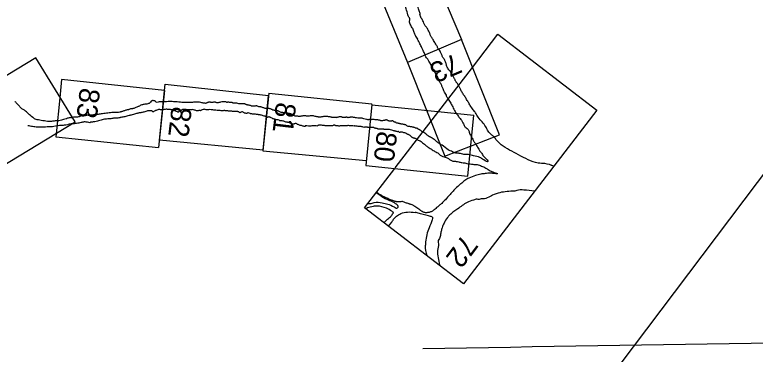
# Model space of a CAD drawing. Extents: x 3879599 to 3900814, y 146526 to 168888.
# Drawn here: x 3883542 to 3885674, y 156492 to 157470 of the extents above; entities that cross this region are included whole.
import ezdxf

# ---------------------------------------------------------------- set-up
doc = ezdxf.new("R2010")
doc.units = 0
for name, color, linetype in [('V-ANNO-NPLT', 7, 'Continuous'), ('V-GRID-FRAM', 7, 'Continuous'), ('V-GRID-MAJR', 7, 'Continuous')]:
    doc.layers.add(name, color=color, linetype=linetype)

msp = doc.modelspace()

# ---------------------------------------------------------------- linework, layer by layer
at = {"layer": 'V-ANNO-NPLT'}
for p, q in [((3884828.5, 157398.7), (3884672.7, 157332)), ((3884559.4, 156925.5), (3884558.4, 156925.5)), ((3884618.4, 156860.4), (3884627.5, 156871.7))]:
    msp.add_line(p, q, dxfattribs=at)
for points in [[(3884713, 157670.7), (3884559.8, 157608.4), (3884672.7, 157332)], [(3884713, 157670.7), (3884828.5, 157398.7)], [(3884933.3, 157413.5), (3885217.9, 157194.6), (3884833.8, 156694.8), (3884549, 156913.5)], [(3884860.1, 157318.3), (3884933.3, 157413.5)], [(3884828.5, 157398.7), (3884672.7, 157332), (3884780.8, 157062.4), (3884937.4, 157123.8)], [(3884937.4, 157123.8), (3884828.5, 157398.7)], [(3883602.8, 157345.6), (3883333.7, 157182.3), (3883446.8, 156998.1), (3883716.1, 157161.4)], [(3883716.1, 157161.4), (3883602.8, 157345.6)], [(3884637.5, 157028.6), (3884860.1, 157318.3)], [(3883973.7, 157251.6), (3883677.2, 157283.4), (3883672, 157230.6)], [(3883958.8, 157108.9), (3883975.6, 157269.5), (3884273, 157237)], [(3883973.7, 157251.6), (3883956.5, 157087.1)], [(3884273.7, 157243.6), (3884256.8, 157077.8), (3884554.2, 157050)], [(3884257, 157080.1), (3884273, 157237)], [(3884273.7, 157243.6), (3884570.4, 157212.9)], [(3883672, 157230.6), (3883661.8, 157126.9)], [(3884570.3, 157211.4), (3884552.7, 157035.1), (3884847.1, 157005.1), (3884855.7, 157092.8)], [(3884570.2, 157210.5), (3884760.7, 157191.1)], [(3884570.3, 157211), (3884570.4, 157212.9)], [(3884759.9, 157190.9), (3884864.2, 157180.3)], [(3884855.7, 157092.8), (3884864.2, 157180.3)], [(3883661.8, 157126.9), (3883660.9, 157117.7), (3883956.5, 157087.1)], [(3884257, 157080.1), (3883958.8, 157108.9)], [(3884554.2, 157050), (3884554.2, 157050)], [(3884549, 156913.5), (3884636.2, 157027)]]:
    msp.add_lwpolyline(points, dxfattribs=at)
for points in [[(3884674.3, 157469.8), (3884669.1, 157487.1), (3884666, 157498), (3884662.6, 157506.4), (3884660.2, 157516.1), (3884658, 157524.6), (3884655.6, 157532.1), (3884654.3, 157538.2), (3884652.2, 157548.3), (3884650.7, 157561.3), (3884649.3, 157577.1), (3884649.3, 157587.7), (3884647.8, 157598.5), (3884647.9, 157605.7), (3884647.5, 157615), (3884647.4, 157618.4)], [(3884752.8, 157387.7), (3884749.7, 157393.1), (3884746.5, 157398.9), (3884741.5, 157406.1), (3884737.8, 157413.7), (3884733.9, 157422.9), (3884731.6, 157427.5), (3884729, 157432.4), (3884723.7, 157438), (3884720.2, 157445.9), (3884717.1, 157452.6), (3884715.3, 157456.8), (3884712.4, 157460.1), (3884710.7, 157465.6), (3884708.8, 157470.8), (3884709.3, 157473.2), (3884707.7, 157478.7), (3884705.8, 157483.9), (3884703.5, 157490.4), (3884702.2, 157495.2), (3884700.9, 157499.4), (3884700, 157501.8)], [(3884687, 157431), (3884686.2, 157432.5), (3884683.6, 157437.9), (3884680.9, 157442.8), (3884679, 157448.6), (3884678.6, 157452.1), (3884680, 157455.7), (3884678.3, 157461.2), (3884676.1, 157464.8), (3884674.3, 157469.8)], [(3884687, 157431), (3884691.1, 157419.7), (3884694.7, 157410.8), (3884701.8, 157399.2)], [(3884724.1, 157354), (3884722.2, 157359.2), (3884719.4, 157363.8), (3884716.2, 157370.9), (3884712.9, 157377.3), (3884710.2, 157383.2), (3884707.2, 157389.3), (3884703.6, 157395.9), (3884701.9, 157399.1), (3884701.8, 157399.2)], [(3884819.8, 157265.9), (3884818.7, 157268.3), (3884817.1, 157271.4), (3884815.3, 157273.3), (3884813.6, 157274.7), (3884811.9, 157277.9), (3884810.6, 157280.3), (3884808.9, 157284), (3884807.3, 157286.7), (3884805.5, 157290.9), (3884803.4, 157293.5), (3884801.3, 157298.9), (3884799.4, 157301.8), (3884797.1, 157306), (3884793.6, 157309.2), (3884790, 157314), (3884787.6, 157318.6), (3884785.5, 157323.6), (3884784.3, 157327.8), (3884783.6, 157331.6), (3884781.5, 157336.1), (3884779.5, 157340.5), (3884777.3, 157344.1), (3884774.9, 157347), (3884773.2, 157350.6), (3884771.7, 157354.6), (3884770, 157358.3), (3884768.2, 157362.5), (3884765.3, 157367.6), (3884761.7, 157371.9), (3884758, 157379), (3884755.5, 157383.4), (3884752.8, 157387.7)], [(3884790.1, 157227.1), (3884785.6, 157235.6), (3884783.7, 157241.3), (3884779.7, 157246.8), (3884776.6, 157254), (3884773.1, 157261.9), (3884769.6, 157269.8), (3884767.3, 157273.9), (3884763.6, 157282), (3884760.5, 157288.7), (3884757.5, 157294.3), (3884754.4, 157298.6), (3884752.6, 157303.3), (3884751.1, 157307.8), (3884749.6, 157311.3), (3884745.7, 157313.9), (3884744, 157318.1), (3884741.7, 157321.8), (3884740, 157325.5), (3884737.9, 157330.4), (3884734.4, 157336), (3884729.9, 157343.7), (3884726.1, 157348.2), (3884724.1, 157354)], [(3884927.6, 157110.8), (3884921.1, 157118.9), (3884913.9, 157124.7), (3884905.6, 157134.2), (3884898.1, 157147.2), (3884888.3, 157160.9), (3884876.3, 157174.5), (3884868.8, 157187.4), (3884862.4, 157195.5), (3884853.6, 157208.3), (3884847.7, 157218.1), (3884841.8, 157228.2), (3884836.2, 157237.2), (3884832.9, 157241.8), (3884827.4, 157251.1), (3884823.8, 157259), (3884819.8, 157265.9)], [(3883594.2, 157174.2), (3883581.7, 157184.7), (3883570.7, 157194.5), (3883562.5, 157199.2), (3883555.6, 157206.6), (3883548.1, 157214), (3883545.1, 157217.9), (3883542.5, 157219.8)], [(3883942.5, 157221.7), (3883939.9, 157222.6), (3883938, 157222.2), (3883935.3, 157220.8), (3883930.3, 157215.5), (3883927.3, 157213.7), (3883922.8, 157212.5), (3883917.1, 157211.8), (3883911.7, 157211), (3883908.2, 157209.9), (3883903.2, 157208.1), (3883898.8, 157205.8), (3883895.5, 157204.6), (3883891.3, 157202.5), (3883886.6, 157200.7), (3883882.7, 157199.4), (3883879.5, 157199), (3883872, 157197.3), (3883870.1, 157196.2), (3883866.4, 157195.6), (3883862.2, 157194.7), (3883858.2, 157193.4), (3883854, 157191.7), (3883850.8, 157190.6), (3883848.4, 157190), (3883845.6, 157189.3), (3883844.8, 157189)], [(3884037, 157217.2), (3884028.2, 157217.1), (3884019, 157217.7), (3884009.8, 157218.6), (3883999.1, 157219.4), (3883992.8, 157219.6), (3883984, 157219.5), (3883974.4, 157219.1), (3883970.1, 157219.4), (3883963.8, 157219.2), (3883958.4, 157219), (3883952.7, 157217.4), (3883947.6, 157219.5), (3883946.3, 157221.5), (3883944, 157221.8), (3883942.5, 157221.7)], [(3884095, 157215.3), (3884094.3, 157215), (3884091.1, 157214.6), (3884087.1, 157215.2), (3884083.2, 157215.7), (3884077.9, 157216.7), (3884070.3, 157218), (3884062.9, 157217.7), (3884060.2, 157218), (3884054.4, 157217.1), (3884045.5, 157216.9), (3884042.7, 157217.1), (3884039.3, 157217.3), (3884037, 157217.2)], [(3884105.3, 157217.7), (3884103.2, 157218.1), (3884100.3, 157217.7), (3884097.7, 157217), (3884096, 157216.1), (3884095, 157215.3)], [(3884154.7, 157217.5), (3884153.2, 157217.4), (3884149.8, 157218.5), (3884146.3, 157219), (3884142.4, 157218.9), (3884134.6, 157218.1), (3884129.9, 157216.6), (3884125.5, 157216.3), (3884121.9, 157216.6), (3884119.9, 157217.8), (3884114.7, 157217.8), (3884110, 157217.1), (3884106.7, 157217.4), (3884105.3, 157217.7)], [(3884168.1, 157216.6), (3884165, 157217.1), (3884162.1, 157217.4), (3884158.4, 157217.5), (3884156.1, 157217.9), (3884154.7, 157217.5)], [(3884206.8, 157211.9), (3884205.5, 157212.5), (3884203.9, 157212.9), (3884199.7, 157213), (3884195.8, 157213.2), (3884191.5, 157213.1), (3884187.4, 157212.8), (3884181.4, 157214.7), (3884176.6, 157215), (3884172.6, 157215.3), (3884169.8, 157215.9), (3884168.1, 157216.6)], [(3884790.1, 157227.1), (3884797.4, 157214.7), (3884803, 157204.3), (3884810, 157190.7), (3884816.7, 157181.4), (3884822.5, 157172.9), (3884826.6, 157168.3), (3884831.5, 157160.5), (3884836.1, 157150.9), (3884838.1, 157147.2), (3884842.3, 157144.2), (3884847.2, 157139.3), (3884850.9, 157131.4), (3884852.6, 157126.1), (3884856.1, 157119.3), (3884862.3, 157108.5), (3884866.2, 157101.7), (3884871.8, 157093.4), (3884877.9, 157082.1), (3884883.1, 157075), (3884883.9, 157074.3), (3884889.8, 157064.7), (3884897.3, 157056.7), (3884902.3, 157051.8), (3884904.5, 157047.1), (3884892.4, 157051.8), (3884881.1, 157058.8), (3884863.4, 157063.2), (3884848.7, 157066.9), (3884835.5, 157067.4), (3884822, 157070.3), (3884811.9, 157071.4), (3884802.1, 157075.3), (3884790.5, 157080.6), (3884772.4, 157094), (3884763, 157099.5), (3884755.2, 157105.6), (3884747.3, 157112.1), (3884735.9, 157118.4), (3884728.1, 157124.8), (3884717, 157132.9)], [(3883942.2, 157190.1), (3883941.4, 157190.2), (3883940, 157190.4), (3883938.5, 157192.2), (3883934.3, 157193), (3883930, 157193.2), (3883924.8, 157192.8), (3883919.8, 157191.3), (3883914.1, 157189.1), (3883909.5, 157188.6), (3883905, 157187.7), (3883900.2, 157187), (3883896.2, 157186.3), (3883892.4, 157184.9), (3883887.5, 157183.2), (3883880, 157181.5), (3883875.3, 157180.1), (3883871.3, 157179.1), (3883864.5, 157177.8), (3883859.3, 157175.8), (3883853.7, 157175.1), (3883847.4, 157173.7), (3883844.7, 157173.2)], [(3884018.3, 157194.1), (3884015.2, 157192.3), (3884014.7, 157190.8), (3884013.6, 157189.5), (3884011.8, 157189.6), (3884009, 157190.9), (3884005.6, 157192), (3884000.2, 157193.7), (3883995.2, 157195.5), (3883990.4, 157196.7), (3883983.6, 157196.7), (3883980.4, 157197.6), (3883975.3, 157197.2), (3883972.3, 157196.7), (3883966.9, 157196.4), (3883961.9, 157196.2), (3883957.9, 157196.8), (3883949.6, 157194.1), (3883946.1, 157193), (3883942.2, 157190.1)], [(3884077.6, 157193.4), (3884075.3, 157193.7), (3884072.5, 157193.7), (3884068.3, 157192.9), (3884063.6, 157194), (3884059.6, 157195.3), (3884054.6, 157196.4), (3884049.2, 157196.1), (3884043.5, 157195.9), (3884039.6, 157196.1), (3884032.5, 157196.6), (3884027.1, 157196.7), (3884023.1, 157196.1), (3884021.1, 157194.1), (3884018.3, 157194.1)], [(3884136.3, 157193.3), (3884130.1, 157194.2), (3884124.7, 157194.4), (3884118.6, 157195.1), (3884112.2, 157195.6), (3884102.8, 157196.4), (3884097, 157195.9), (3884093.7, 157195.9), (3884088, 157197.6), (3884084.7, 157196.7), (3884079.9, 157194.7), (3884078.9, 157194.2), (3884076.9, 157192.9)], [(3884183.7, 157191.2), (3884179.8, 157191.2), (3884177.2, 157190.7), (3884171.6, 157191), (3884167.2, 157191.9), (3884161.4, 157192.4), (3884157.9, 157192.5), (3884153.8, 157192.9), (3884149.8, 157193.2), (3884147.2, 157193.7), (3884144.2, 157193.5), (3884140.4, 157192.7), (3884137.8, 157193.1), (3884136.3, 157193.3)], [(3884214.9, 157209.5), (3884213.4, 157209.6), (3884211.6, 157210.1), (3884209.1, 157210.7), (3884208.2, 157211.1), (3884206.8, 157211.9)], [(3884281.8, 157197.2), (3884278.5, 157198.3), (3884275.1, 157199.7), (3884270.6, 157199.8), (3884264.7, 157200), (3884261.6, 157200.5), (3884257.8, 157201.9), (3884253.9, 157203.1), (3884250.4, 157204.3), (3884247, 157204.5), (3884244.8, 157204.9), (3884241.2, 157206.1), (3884239.3, 157207.4), (3884236.4, 157207), (3884232.6, 157206.3), (3884227.7, 157206.6), (3884224.1, 157206.9), (3884221.3, 157208.2), (3884217.6, 157208.9), (3884214.9, 157209.5)], [(3884353.5, 157177.5), (3884349.4, 157178.1), (3884345.4, 157179.4), (3884342.7, 157180.6), (3884339.2, 157183.4), (3884334.6, 157184.5), (3884331.1, 157185.4), (3884328.9, 157185.8), (3884325, 157186.7), (3884319, 157186.9), (3884315.9, 157187.4), (3884312.6, 157188.1), (3884309.2, 157188.6), (3884305.3, 157189.8), (3884302.6, 157191.7), (3884299.2, 157192.7), (3884296.1, 157193.3), (3884292.8, 157194), (3884290.1, 157194.2), (3884287.3, 157194.8), (3884284, 157195.9), (3884282.4, 157197.1), (3884281.8, 157197.2)], [(3883690.3, 157169.7), (3883683, 157167.7), (3883676.7, 157166), (3883668.9, 157164.2), (3883661.1, 157164.6), (3883656.1, 157163.4), (3883645.3, 157162.7), (3883636.3, 157162.6), (3883627.6, 157163.8), (3883618.6, 157165.2), (3883610.2, 157166.7), (3883603.8, 157168.3), (3883599.4, 157170.1), (3883595.1, 157173.5), (3883594.2, 157174.2)], [(3883751.4, 157180.4), (3883748.4, 157179.9), (3883745.2, 157178.8), (3883742.5, 157178.2), (3883739.5, 157178.4), (3883736.7, 157178.8), (3883731.4, 157177.2), (3883728.2, 157176.1), (3883723.4, 157175.1), (3883719.4, 157174.6), (3883714.7, 157174.4), (3883711.2, 157174.5), (3883707.8, 157173.1), (3883704.3, 157173.2), (3883700.8, 157173.3), (3883696.4, 157172.3), (3883692.1, 157170.8), (3883690.3, 157169.7)], [(3883844.8, 157189), (3883836.8, 157188.3), (3883831.8, 157188.1), (3883825.5, 157188.3), (3883810.1, 157186.4), (3883794.5, 157184.7), (3883782, 157182.7), (3883772.7, 157182.4), (3883765, 157180.8), (3883758, 157179.7), (3883751.4, 157180.4)], [(3883844.8, 157173.3), (3883839.5, 157171.9), (3883826.8, 157171.4), (3883816.8, 157169.8), (3883803.4, 157169.2), (3883791, 157166.2), (3883776.4, 157162.7), (3883768.5, 157160.9), (3883763.3, 157160.5), (3883758.5, 157158.6), (3883758.4, 157158.2)], [(3884267.5, 157175.2), (3884264.8, 157177), (3884262.9, 157177.2), (3884257.6, 157178.6), (3884253.1, 157180.2), (3884248.7, 157181.5), (3884244.3, 157181.8), (3884241.2, 157182.3), (3884235.4, 157183.1), (3884230.2, 157183.4), (3884226.7, 157183.5), (3884223.2, 157184.4), (3884219.7, 157185.3), (3884214.3, 157187), (3884211.7, 157186.2), (3884210.6, 157185.5), (3884206.4, 157185.9), (3884203.6, 157186.5), (3884201.3, 157188.4), (3884198.4, 157189.7), (3884194.1, 157189.6), (3884192, 157188.1), (3884190.8, 157187.4), (3884188.3, 157189.1), (3884186.5, 157190.2), (3884184.8, 157190.9), (3884183.5, 157191.3)], [(3884327.1, 157160), (3884322.9, 157160.6), (3884319, 157162.1), (3884314.7, 157163.6), (3884310.3, 157164.2), (3884305.7, 157164.1), (3884303.2, 157165.7), (3884297.4, 157167.1), (3884293.6, 157167.9), (3884288.8, 157169.2), (3884285.6, 157170.4), (3884280.3, 157173), (3884277.2, 157174.5), (3884274.6, 157175.6), (3884272.2, 157175), (3884269.9, 157174.2), (3884268.2, 157174.9), (3884267.5, 157175.2)], [(3884415, 157175.7), (3884414.3, 157175.7), (3884409.9, 157176.6), (3884407.5, 157176.9), (3884401.9, 157178.4), (3884397.2, 157179), (3884392.6, 157178.4), (3884387, 157177.8), (3884381.8, 157177.8), (3884378.3, 157178.6), (3884373.9, 157178.9), (3884369.6, 157177.8), (3884366.2, 157177.6), (3884360.9, 157176.7), (3884357.1, 157177.2), (3884355.3, 157177.3), (3884353.5, 157177.5)], [(3884427.9, 157175.8), (3884425.3, 157175.3), (3884421.6, 157174.9), (3884418.1, 157174.9), (3884416, 157175), (3884414.9, 157175.7)], [(3884442.4, 157176.6), (3884438.9, 157176.3), (3884436.4, 157176.7), (3884432.6, 157176.5), (3884429.5, 157176.1), (3884427.9, 157175.8)], [(3884487.1, 157173.5), (3884486.5, 157173.5), (3884484.8, 157174.2), (3884484, 157174.9), (3884481.8, 157175.7), (3884479.1, 157175.6), (3884477, 157175.3), (3884474.7, 157175.2), (3884473, 157174.7), (3884470.9, 157174.1), (3884468.8, 157173.9), (3884467.1, 157173.3), (3884465.4, 157173.7), (3884463.1, 157173.9), (3884461.3, 157174.1), (3884458.4, 157174.1), (3884455.7, 157174), (3884453.7, 157174.3), (3884452.1, 157174.7), (3884448.1, 157175.7), (3884445.4, 157175.9), (3884442.4, 157176.6)], [(3884495.7, 157174.3), (3884494, 157174.1), (3884491.8, 157174), (3884489.4, 157173.8), (3884487.1, 157173.5)], [(3884504.6, 157173.9), (3884502.2, 157173.2), (3884500.7, 157173.7), (3884498, 157174.3), (3884495.7, 157174.3)], [(3884597.1, 157164), (3884596.9, 157163.9), (3884595.6, 157164.6), (3884594.5, 157165.2), (3884591, 157166.2), (3884587.1, 157166.6), (3884584, 157166.9), (3884581.5, 157166.8), (3884579.4, 157167.2), (3884574.6, 157168), (3884571.4, 157168.2), (3884568.8, 157167.2), (3884566.5, 157167.8), (3884564.2, 157167.9), (3884563, 157167.9), (3884560.4, 157167.3), (3884557.3, 157167.6), (3884554.5, 157168.3), (3884546.9, 157169.8), (3884542.2, 157171.5), (3884536.7, 157171.6), (3884533.5, 157172), (3884529.9, 157172.1), (3884523.1, 157173.1), (3884519.1, 157173.8), (3884516, 157174.5), (3884510.7, 157175), (3884509.2, 157175), (3884507.4, 157174), (3884504.6, 157173.9)], [(3883663.7, 157149.4), (3883646.5, 157146.7), (3883635.5, 157146.5), (3883616.8, 157145.6), (3883608.3, 157145.7), (3883600.2, 157146.8), (3883586.9, 157148.8), (3883580.3, 157150.1)], [(3883758.5, 157158.4), (3883752.1, 157160.3), (3883748.3, 157160.6), (3883742.2, 157160.9), (3883733.2, 157159.2), (3883720.4, 157156.7), (3883710.5, 157155.6), (3883704.8, 157155.2), (3883693.8, 157152.8), (3883685, 157151.3), (3883671.6, 157150.3), (3883663.7, 157149.4)], [(3884416.6, 157151.4), (3884414.8, 157150.6), (3884414.1, 157149.8), (3884409.7, 157149.5), (3884405.1, 157149.4), (3884398, 157149.5), (3884392, 157148.8), (3884383.4, 157149.3), (3884380.3, 157149.5), (3884378.7, 157149.5), (3884378.1, 157148.7), (3884377.9, 157148.1), (3884375.3, 157148), (3884371.6, 157148.7), (3884367.5, 157150.4), (3884364, 157150.9), (3884360, 157152.7), (3884356.1, 157153.9), (3884354.3, 157155.7), (3884351, 157156.4), (3884348, 157155.9), (3884345.6, 157154.9), (3884342.9, 157154.8), (3884338.7, 157155.9), (3884334.7, 157157.4), (3884331.2, 157159), (3884328.4, 157159.6), (3884327.1, 157160)], [(3884519.4, 157149.2), (3884512.5, 157149.9), (3884508.4, 157150), (3884505.9, 157150), (3884501, 157150.4), (3884497.2, 157149.9), (3884493.1, 157150), (3884491.1, 157149.6), (3884486.1, 157149.8), (3884481.5, 157149.6), (3884477.3, 157149.1), (3884473.5, 157149.3), (3884470.1, 157149.8), (3884466.7, 157149.9), (3884465.1, 157150.8), (3884461.5, 157151.8), (3884458.7, 157150.8), (3884454.6, 157149.6), (3884451.2, 157149.8), (3884447.4, 157149.9), (3884443.5, 157149.5), (3884438.5, 157150), (3884434, 157150.4), (3884430.4, 157150.7), (3884425.8, 157151.4), (3884422.3, 157151.4), (3884419.2, 157151.9), (3884416.6, 157151.4)], [(3884611, 157166.6), (3884607.9, 157166), (3884605, 157165.1), (3884600.8, 157164.5), (3884598.2, 157164.2), (3884597.1, 157164)], [(3884633.9, 157161.7), (3884632.4, 157162.7), (3884631.5, 157163.4), (3884629.9, 157164.4), (3884628.5, 157164.3), (3884626.8, 157163.6), (3884625.3, 157163.2), (3884624.1, 157162.9), (3884621.3, 157163.1), (3884619.7, 157163.5), (3884618.4, 157164.2), (3884616.7, 157165), (3884615.4, 157165.7), (3884614, 157166.2), (3884612.6, 157166.7), (3884611, 157166.6)], [(3884657.4, 157154.3), (3884656.5, 157154.2), (3884655.3, 157154.6), (3884654.2, 157155.2), (3884652.5, 157155.6), (3884652.1, 157155.6), (3884650.8, 157155.5), (3884650.3, 157155.2), (3884649.6, 157156.2), (3884646.8, 157156.9), (3884644.5, 157157.5), (3884640.5, 157158.5), (3884640.1, 157159.5), (3884638.8, 157159.9), (3884636.8, 157160), (3884635.4, 157160.1), (3884634.9, 157160.6), (3884633.9, 157161.7)], [(3884668.1, 157152.6), (3884665.7, 157153.1), (3884663, 157153.5), (3884659.9, 157154.1), (3884657.4, 157154.3)], [(3884717, 157132.9), (3884712, 157135.1), (3884709.8, 157136.9), (3884708, 157138.1), (3884706.2, 157138.9), (3884704.7, 157140.1), (3884703.1, 157141.1), (3884701.4, 157142.1), (3884699.2, 157142.6), (3884697.1, 157142.8), (3884694.8, 157144), (3884692, 157145), (3884690.1, 157145.7), (3884687.1, 157146.2), (3884684.7, 157146.6), (3884683, 157146.7), (3884680.1, 157147.6), (3884677.8, 157147.8), (3884672.6, 157149), (3884669.9, 157151.2), (3884668.1, 157152.6)], [(3884612, 157139.1), (3884608.1, 157139), (3884606.6, 157139.5), (3884604.8, 157139.7), (3884601.9, 157140.4), (3884600.1, 157140.6), (3884596.2, 157140.2), (3884589.7, 157140.5), (3884587.7, 157140.8), (3884586, 157142.2), (3884583.5, 157142.3), (3884580.4, 157142.8), (3884578.3, 157143.5), (3884576.4, 157144.7), (3884573.4, 157144.6), (3884571.4, 157144.9), (3884569.6, 157145.4), (3884565.9, 157144.8), (3884562.8, 157145), (3884560.7, 157145.1), (3884557.6, 157145.6), (3884555.8, 157145.8), (3884551.5, 157146), (3884547.1, 157145.4), (3884543.2, 157146.5), (3884539.2, 157147.5), (3884534.1, 157148), (3884530.7, 157148.2), (3884526, 157148.7), (3884521.8, 157149.5), (3884519.4, 157149.2)], [(3884700, 157110.2), (3884697.6, 157111.9), (3884694.1, 157113.7), (3884691.9, 157114.1), (3884689.4, 157115.1), (3884687.4, 157115.8), (3884685.6, 157117.5), (3884683.6, 157119.1), (3884681.5, 157120.5), (3884678.9, 157122.8), (3884677, 157124.1), (3884675, 157124.7), (3884672.6, 157125.3), (3884669.7, 157127.3), (3884666.8, 157129), (3884663.6, 157129.3), (3884660.4, 157130.6), (3884656.9, 157131.4), (3884654.6, 157131.7), (3884651.8, 157131.4), (3884650, 157130.8), (3884648.1, 157132.1), (3884646.6, 157133), (3884644.6, 157132.9), (3884642.8, 157133.1), (3884640.8, 157133.7), (3884638.4, 157134.4), (3884635.5, 157135.1), (3884633.5, 157135.4), (3884630.9, 157136.2), (3884623.9, 157137.9), (3884618.7, 157139.5), (3884616.1, 157139), (3884614.3, 157139.5), (3884612, 157139.1)], [(3884700, 157110.2), (3884712.3, 157104.3), (3884716.6, 157101), (3884722, 157096.6), (3884728.2, 157090.7), (3884732.1, 157088.1), (3884735.6, 157085.9), (3884744.2, 157080.8), (3884754.8, 157074.4), (3884760.6, 157071.7), (3884764.4, 157067.7), (3884778.2, 157060.3), (3884784.7, 157058.1), (3884792.4, 157054.3), (3884799.5, 157049.6), (3884808, 157047.8), (3884813.4, 157047.1), (3884820.3, 157045.9), (3884829.5, 157044.1), (3884837.6, 157042.8), (3884844.1, 157041.2), (3884853.5, 157040.3), (3884861.3, 157038.9), (3884867.2, 157038.2), (3884873.5, 157038.1), (3884886.1, 157034), (3884898.3, 157028.2), (3884905.5, 157023.5), (3884916, 157018.1), (3884925.5, 157014.7), (3884931.8, 157012.1), (3884921.9, 157012.3), (3884912, 157013.6), (3884896.3, 157012), (3884884.3, 157010.7), (3884868.9, 157006.2), (3884849.3, 156999), (3884837.9, 156992.2), (3884828.9, 156984.6), (3884820.8, 156978.2), (3884808.4, 156966.3), (3884800, 156957.1), (3884790.7, 156946.7), (3884781.9, 156936.9), (3884771.5, 156926.4), (3884764.5, 156920.1), (3884760.4, 156916.8)], [(3885094.3, 157033.5), (3885068.7, 157040.9), (3885048.9, 157042.3), (3884992.8, 157066.5), (3884942.8, 157095.3), (3884927.6, 157110.8)], [(3885094.2, 157033.5), (3885068.7, 157040.9), (3885048.9, 157042.3), (3884992.8, 157066.5), (3884942.8, 157095.3), (3884927.6, 157110.8)], [(3884589.9, 156954.4), (3884587.7, 156956), (3884586.4, 156957.1), (3884583.9, 156958.8)], [(3885039, 156961.9), (3885007.7, 156964.7), (3884987.7, 156963.5), (3884981.8, 156961.8), (3884975.7, 156961.3), (3884933.7, 156955.8), (3884922, 156951.9), (3884906.7, 156944.1), (3884889.9, 156939), (3884884.6, 156939.4), (3884878.8, 156937.2), (3884873.7, 156938), (3884862.8, 156936), (3884844.5, 156928.9), (3884816.9, 156910), (3884806.5, 156903.1), (3884794.6, 156892.8), (3884788, 156886), (3884778.2, 156869.5), (3884772.4, 156856.1), (3884769.8, 156845.8), (3884768.6, 156840.7), (3884766.1, 156827.8), (3884761.1, 156816.3), (3884762.1, 156809.9), (3884759.6, 156790), (3884764.7, 156749), (3884764.7, 156747.8)], [(3884559.4, 156925.5), (3884564.7, 156925.6), (3884577.4, 156928.8), (3884600.1, 156927.9), (3884634.2, 156916), (3884644.6, 156913.2), (3884646, 156917.2), (3884638.6, 156925.4), (3884629.3, 156930.9), (3884614.3, 156937.1), (3884594.3, 156948.6), (3884582.6, 156957.2)], [(3884639.7, 156931.3), (3884635.8, 156932.3), (3884630.4, 156934.1), (3884627.1, 156935.4), (3884624.4, 156936.3), (3884621.3, 156937.2), (3884616.6, 156940.6), (3884611.3, 156942.6), (3884607.7, 156944.3), (3884604.6, 156945.4), (3884597.1, 156949.7), (3884592.5, 156952.3), (3884589.9, 156954.4)], [(3884628.1, 156903.8), (3884612.2, 156912.2), (3884585.7, 156918.4), (3884574.1, 156917.5), (3884557.8, 156913), (3884552.9, 156910.5)], [(3884691.2, 156919.3), (3884688.3, 156921), (3884683.9, 156922.7), (3884680.5, 156923.8), (3884677.9, 156924.5), (3884674.9, 156925.9), (3884669.6, 156927.3), (3884665.3, 156928.8), (3884660.6, 156930.7), (3884656.4, 156931.4), (3884652, 156930.7), (3884647.9, 156930.3), (3884644.2, 156930.5), (3884641.1, 156931.2), (3884639.7, 156931.3)], [(3884760.4, 156916.8), (3884756.6, 156914.2), (3884752.3, 156909.8), (3884750.8, 156908.8), (3884747.9, 156906.7), (3884745.2, 156904.2), (3884741.1, 156902.3), (3884737.3, 156901), (3884733.1, 156900), (3884728.6, 156899.5), (3884724.9, 156899.4), (3884720.7, 156900.2), (3884715.3, 156902.6), (3884712, 156904.4), (3884708.3, 156907.5), (3884703.1, 156911.7), (3884700.3, 156913.7), (3884694.1, 156917.6), (3884691.2, 156919.3)], [(3884605.1, 156870.4), (3884612.7, 156878.3), (3884623.8, 156887.7), (3884629.9, 156895.8)], [(3884627.5, 156871.7), (3884632.9, 156880.3), (3884644.4, 156891.5), (3884653.5, 156896.8), (3884673.1, 156901.4), (3884694.7, 156899.9)], [(3884628.1, 156903.8), (3884630.3, 156901.9), (3884631.3, 156900.3), (3884631.6, 156898.2), (3884629.9, 156895.8)], [(3884745.1, 156886.8), (3884736.6, 156889.5), (3884729.6, 156891.3), (3884721.8, 156893.3), (3884714, 156895.3), (3884707.1, 156897.3), (3884700.8, 156899.1), (3884694.7, 156899.9)], [(3884745.1, 156886.8), (3884743.7, 156878.7), (3884734.9, 156855.9), (3884725.2, 156815.4), (3884724.2, 156804.4), (3884728.8, 156776.5), (3884728.9, 156776.3)]]:
    msp.add_spline(points, degree=3, dxfattribs=at)
at = {"layer": 'V-GRID-FRAM'}
msp.add_lwpolyline([(3898776.6, 160226.4), (3889730.7, 148455.2), (3882888.9, 153284.4), (3891901.5, 165241.3), (3898776.6, 160226.4)], dxfattribs=at)
at = {"layer": 'V-GRID-MAJR'}
msp.add_spline([(3884717.1, 156508.2), (3888748.3, 156574.8), (3894080.4, 156663.6), (3896663.2, 156706.9)], degree=3, dxfattribs=at)

# ---------------------------------------------------------------- texts
at = {"layer": 'V-ANNO-NPLT'}
for s, rotation, p in [('73', 203.1706, (3884811.7, 157359.8)), ('83', 263.1706, (3883730.3, 157261.2)), ('81', 263.1706, (3884294.9, 157219.7)), ('82', 263.1706, (3883994.3, 157207.4)), ('80', 263.1706, (3884585.6, 157136.3)), ('72', 233.1706, (3884832.8, 156840.1))]:
    msp.add_text(s, height=58.5, rotation=rotation, dxfattribs=at).set_placement(p)

doc.saveas('drawing.dxf')
